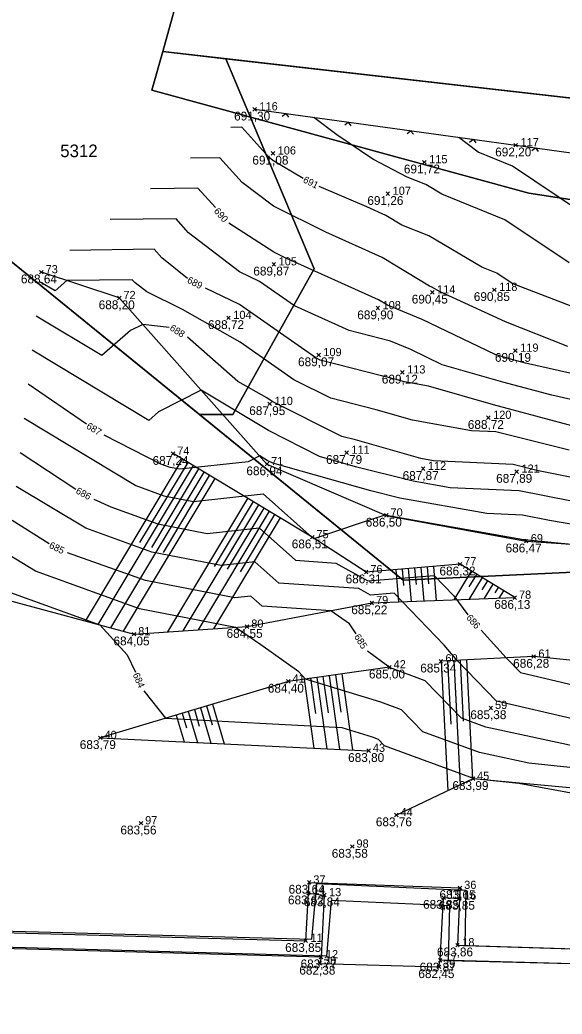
# Model space of a CAD drawing. Extents: x -439750 to -439180, y -1258684 to -1258308.
# Drawn here: x -439519.38 to -439502.17, y -1258511.26 to -1258479.7 of the extents above; entities that cross this region are included whole.
import ezdxf

# ---------------------------------------------------------------- set-up
doc = ezdxf.new("R2010")
doc.units = 0
for name, color, linetype in [('BODY', 7, 'Continuous'), ('CISBOD', 7, 'Continuous'), ('HRANA', 7, 'Continuous'), ('KATASTER', 7, 'Continuous'), ('POLOHOPIS', 7, 'Continuous'), ('SRAFY', 7, 'Continuous'), ('UOV', 7, 'Continuous'), ('VRSTEV', 7, 'Continuous'), ('VYSKY', 7, 'Continuous')]:
    doc.layers.add(name, color=color, linetype=linetype)

# ---------------------------------------------------------------- blocks, each defined once
blk = doc.blocks.new('KRIZEK')
for p, q in [((-2, 0), (2, 0)), ((0, 2), (0, -2))]:
    blk.add_line(p, q)
blk = doc.blocks.new('2123')
blk.add_lwpolyline([(-0.5, -0.5), (0, 0), (0.5, -0.5)])

msp = doc.modelspace()

# ---------------------------------------------------------------- linework, layer by layer
at = {"layer": 'HRANA'}
for points in [[(-439511.54, -1258493.8), (-439516.23, -1258488.53), (-439518.7, -1258487.71)], [(-439519.92, -1258498.08), (-439515.76, -1258499.2), (-439512.17, -1258498.96), (-439508.21, -1258498.21), (-439503.67, -1258498.04), (-439505.41, -1258496.98), (-439508.39, -1258497.23), (-439510.1, -1258496.12), (-439514.52, -1258493.47)], [(-439511.54, -1258493.8), (-439507.75, -1258495.43), (-439503.31, -1258496.25), (-439496.67, -1258496.69), (-439488.09, -1258496.97), (-439481.73, -1258497.12), (-439481.16, -1258497.23), (-439475.66, -1258497.77), (-439471.49, -1258498.09)], [(-439471.88, -1258500.9), (-439476.61, -1258500.46), (-439482.49, -1258500.91), (-439485.2, -1258501.28), (-439488.38, -1258501.74), (-439492.71, -1258501.52), (-439497.17, -1258500.51), (-439503.07, -1258499.91), (-439506.02, -1258500.06)], [(-439507.65, -1258500.25), (-439510.86, -1258500.7), (-439516.83, -1258502.49), (-439508.31, -1258502.9)], [(-439475.58, -1258504.53), (-439478.3, -1258506.13), (-439479.11, -1258504.72), (-439487.55, -1258505.34), (-439492.66, -1258505.61), (-439495.41, -1258504.44), (-439498.85, -1258504.36), (-439505, -1258503.79), (-439507.43, -1258504.94)]]:
    msp.add_lwpolyline(points, dxfattribs=at)
at = {"layer": 'KATASTER'}
for points in [[(-439462.74, -1258442.73), (-439465.13, -1258459.21), (-439469.01, -1258485.93), (-439514.85, -1258480.71), (-439509.68, -1258462.08), (-439512.86, -1258458.3), (-439516.51, -1258455.4), (-439520.66, -1258452.66), (-439525.5, -1258450.78), (-439531.73, -1258450.85), (-439536.69, -1258451.87), (-439541.07, -1258454.21), (-439546.64, -1258459.47)], [(-439546.64, -1258459.47), (-439541.07, -1258454.21), (-439536.69, -1258451.87), (-439531.73, -1258450.85), (-439525.5, -1258450.78), (-439520.66, -1258452.66), (-439516.51, -1258455.4), (-439512.86, -1258458.3), (-439509.68, -1258462.08), (-439514.85, -1258480.71), (-439515.19, -1258481.93), (-439503.22, -1258485.2), (-439495.92, -1258486.32), (-439485.72, -1258487.41), (-439470.33, -1258487.62), (-439429.22, -1258494.1), (-439415.96, -1258495.89), (-439399.97, -1258496.98), (-439400.54, -1258499.28), (-439484.47, -1258496.42), (-439507.21, -1258497.49), (-439520.19, -1258486.95), (-439538.17, -1258484.88), (-439548.5, -1258497.7)], [(-439548.5, -1258497.7), (-439538.17, -1258484.88), (-439520.19, -1258486.95), (-439507.21, -1258497.49), (-439484.47, -1258496.42), (-439400.54, -1258499.28), (-439387.09, -1258499.74), (-439411.19, -1258562.66), (-439413.56, -1258566.65), (-439437.77, -1258626.82), (-439438.12, -1258627.38), (-439482.75, -1258611.76), (-439518.67, -1258591.95), (-439550.54, -1258581.84), (-439567.51, -1258574.36), (-439597.45, -1258561.13)]]:
    msp.add_lwpolyline(points, dxfattribs=at)
for points in [[(-439515.19, -1258481.93), (-439514.85, -1258480.71), (-439469.01, -1258485.93), (-439399.61, -1258493.83), (-439399.2, -1258493.87), (-439399.97, -1258496.98), (-439415.96, -1258495.89), (-439429.22, -1258494.1), (-439470.33, -1258487.62), (-439485.72, -1258487.41), (-439495.92, -1258486.32), (-439503.22, -1258485.2)], [(-439543.31, -1258507.99), (-439510.11, -1258508.88), (-439509.96, -1258507.11), (-439505.22, -1258507.33), (-439505.26, -1258509.08), (-439479.78, -1258509.87), (-439475.62, -1258505.39), (-439475.25, -1258505.73), (-439479.41, -1258510.21), (-439505.77, -1258509.57), (-439505.73, -1258507.82), (-439509.5, -1258507.65), (-439509.65, -1258509.42), (-439543.32, -1258508.49)]]:
    msp.add_lwpolyline(points, close=True, dxfattribs=at)
at = {"layer": 'POLOHOPIS'}
for points in [[(-439511.93, -1258482.54), (-439503.64, -1258483.68), (-439495.23, -1258484.84), (-439489.64, -1258485.55), (-439488, -1258485.65), (-439480.93, -1258486.14), (-439472.63, -1258486.56)], [(-439510.22, -1258507.42), (-439510.2, -1258507.08), (-439505.41, -1258507.25), (-439505.43, -1258507.59)], [(-439491.72, -1258509.46), (-439491.73, -1258509.96), (-439498, -1258509.77), (-439506.04, -1258509.55), (-439505.93, -1258507.56)], [(-439505.93, -1258507.56), (-439505.43, -1258507.59), (-439505.49, -1258509.07), (-439497.99, -1258509.3), (-439491.72, -1258509.46)], [(-439509.82, -1258509.45), (-439509.86, -1258509.65), (-439506.08, -1258509.76), (-439506.04, -1258509.55)]]:
    msp.add_lwpolyline(points, dxfattribs=at)
msp.add_lwpolyline([(-439509.72, -1258507.48), (-439509.82, -1258509.45), (-439529.32, -1258508.92), (-439543.52, -1258508.46), (-439543.4, -1258507.94), (-439529.22, -1258508.41), (-439510.31, -1258508.93), (-439510.22, -1258507.42)], close=True, dxfattribs=at)
at = {"layer": 'SRAFY'}
for p, q in [((-439514.227, -1258493.646), (-439517.307, -1258498.783)), ((-439513.884, -1258493.851), (-439516.906, -1258498.891)), ((-439514.056, -1258493.748), (-439515.581, -1258496.293)), ((-439513.541, -1258494.057), (-439516.504, -1258499)), ((-439513.713, -1258493.954), (-439515.209, -1258496.45)), ((-439513.369, -1258494.16), (-439514.837, -1258496.607)), ((-439513.198, -1258494.263), (-439516.103, -1258499.108)), ((-439512.152, -1258494.89), (-439514.694, -1258499.129)), ((-439511.809, -1258495.095), (-439514.208, -1258499.096)), ((-439511.981, -1258494.992), (-439513.216, -1258497.052)), ((-439511.466, -1258495.301), (-439513.722, -1258499.064)), ((-439511.638, -1258495.198), (-439512.801, -1258497.139)), ((-439511.295, -1258495.404), (-439512.387, -1258497.226)), ((-439511.123, -1258495.507), (-439513.236, -1258499.031)), ((-439507.449, -1258497.151), (-439507.363, -1258498.178)), ((-439507.25, -1258497.134), (-439507.207, -1258497.653)), ((-439507.051, -1258497.118), (-439506.963, -1258498.163)), ((-439506.851, -1258497.101), (-439506.807, -1258497.628)), ((-439506.652, -1258497.084), (-439506.563, -1258498.148)), ((-439506.453, -1258497.067), (-439506.408, -1258497.604)), ((-439506.254, -1258497.051), (-439506.163, -1258498.133)), ((-439505.052, -1258497.198), (-439505.61, -1258498.113)), ((-439504.882, -1258497.302), (-439505.126, -1258497.703)), ((-439504.711, -1258497.406), (-439505.13, -1258498.095)), ((-439504.54, -1258497.51), (-439504.715, -1258497.798)), ((-439504.369, -1258497.614), (-439504.651, -1258498.077)), ((-439504.198, -1258497.718), (-439504.305, -1258497.893)), ((-439504.028, -1258497.822), (-439504.172, -1258498.059)), ((-439506.005, -1258500.059), (-439505.797, -1258504.167)), ((-439505.806, -1258500.049), (-439505.703, -1258502.062)), ((-439505.606, -1258500.039), (-439505.405, -1258503.982)), ((-439505.406, -1258500.029), (-439505.308, -1258501.959)), ((-439505.206, -1258500.019), (-439505.014, -1258503.797)), ((-439509.365, -1258500.49), (-439509.198, -1258501.678)), ((-439509.167, -1258500.463), (-439508.828, -1258502.875)), ((-439510.355, -1258500.629), (-439510.048, -1258502.816)), ((-439510.157, -1258500.601), (-439510.001, -1258501.714)), ((-439509.959, -1258500.574), (-439509.642, -1258502.836)), ((-439509.761, -1258500.546), (-439509.6, -1258501.696)), ((-439509.563, -1258500.518), (-439509.235, -1258502.855)), ((-439513.27, -1258501.423), (-439512.893, -1258502.679)), ((-439514.42, -1258501.767), (-439514.165, -1258502.618)), ((-439514.228, -1258501.71), (-439514.09, -1258502.169)), ((-439514.037, -1258501.652), (-439513.741, -1258502.639)), ((-439513.845, -1258501.595), (-439513.687, -1258502.122)), ((-439513.653, -1258501.538), (-439513.317, -1258502.659)), ((-439513.462, -1258501.48), (-439513.284, -1258502.075))]:
    msp.add_line(p, q, dxfattribs=at)
at = {"layer": 'UOV'}
for points in [[(-439520.19, -1258486.95), (-439538.17, -1258484.88), (-439547.11, -1258495.98), (-439553.31, -1258481.48), (-439550.29, -1258478.38), (-439548.77, -1258475.54), (-439547.7, -1258471.18), (-439548.42, -1258468.53), (-439551.33, -1258468.47), (-439546.64, -1258459.47), (-439541.07, -1258454.21), (-439536.69, -1258451.87), (-439531.73, -1258450.85), (-439525.5, -1258450.78), (-439520.66, -1258452.66), (-439516.51, -1258455.4), (-439512.86, -1258458.3), (-439509.68, -1258462.08), (-439514.85, -1258480.71), (-439512.85, -1258480.94), (-439510.04, -1258487.61), (-439512.62, -1258492.23), (-439513.68, -1258492.23)], [(-439484.47, -1258496.42), (-439507.21, -1258497.49), (-439513.68, -1258492.23), (-439512.62, -1258492.23), (-439510.04, -1258487.61), (-439512.85, -1258480.94), (-439399.2, -1258493.87), (-439444.59, -1258496.79), (-439457.07, -1258497.35)]]:
    msp.add_lwpolyline(points, close=True, dxfattribs=at)
at = {"layer": 'VRSTEV'}
for p, q in [((-439517.264, -1258492.538), (-439519.119, -1258491.268)), ((-439519.373, -1258493.43), (-439517.605, -1258494.6)), ((-439518.453, -1258496.331), (-439519.627, -1258495.593))]:
    msp.add_line(p, q, dxfattribs=at)
for points in [[(-439501.945, -1258487.417), (-439503.99, -1258486.045), (-439505.986, -1258485.231), (-439506.497, -1258484.93), (-439507.087, -1258484.692), (-439508.176, -1258484.125), (-439509.324, -1258483.352), (-439510.051, -1258482.798)], [(-439510.387, -1258484.737), (-439511.348, -1258484.164), (-439511.481, -1258484.063), (-439512.341, -1258483.113), (-439512.686, -1258483.117)], [(-439498.592, -1258486.625), (-439499.716, -1258486.844), (-439499.882, -1258486.862), (-439500.133, -1258486.766), (-439503.739, -1258484.346), (-439504.829, -1258483.901), (-439505.445, -1258483.432)], [(-439501.983, -1258490.065), (-439503.965, -1258489.291), (-439506.041, -1258488.34), (-439506.3, -1258488.187), (-439506.377, -1258488.156), (-439507.879, -1258487.248), (-439509.673, -1258486.441), (-439511.336, -1258485.621), (-439512.329, -1258484.861), (-439513.036, -1258484.081), (-439513.963, -1258484.092)], [(-439496.598, -1258488.747), (-439498.657, -1258489.027), (-439500.691, -1258489.246), (-439503.758, -1258488.068), (-439504.242, -1258487.743), (-439504.714, -1258487.551), (-439506.398, -1258486.559), (-439507.252, -1258486.214), (-439507.761, -1258485.907), (-439508.368, -1258485.633), (-439509.881, -1258484.987)], [(-439513.176, -1258485.661), (-439513.177, -1258485.659), (-439513.731, -1258485.048), (-439515.24, -1258485.067)], [(-439500.78, -1258492.004), (-439502.49, -1258491.617), (-439504.054, -1258491.201), (-439505.975, -1258490.647), (-439506.97, -1258490.168), (-439507.617, -1258489.904), (-439508.925, -1258489.567), (-439510.667, -1258488.783), (-439511.781, -1258488.005), (-439512.406, -1258487.697), (-439514.026, -1258486.457), (-439514.425, -1258486.016), (-439516.517, -1258486.043)], [(-439496.117, -1258491.08), (-439496.994, -1258491.129), (-439497.598, -1258491.21), (-439498.471, -1258491.304), (-439500.847, -1258491.155), (-439503.327, -1258490.595), (-439503.763, -1258490.479), (-439504.298, -1258490.324), (-439506.612, -1258489.211), (-439507.713, -1258488.761), (-439507.997, -1258488.59), (-439510.978, -1258487.248), (-439511.323, -1258487.078), (-439512.748, -1258486.152)], [(-439514.067, -1258487.91), (-439514.874, -1258487.255), (-439515.12, -1258486.984), (-439517.793, -1258487.018)], [(-439501.939, -1258493.364), (-439504.272, -1258492.782), (-439505.04, -1258492.745), (-439506.913, -1258492.407), (-439508.067, -1258492.081), (-439509.506, -1258491.714), (-439510.683, -1258491.123), (-439512.391, -1258489.928), (-439514.219, -1258488.895), (-439515.35, -1258488.338), (-439515.723, -1258488.053), (-439515.815, -1258487.951), (-439517.893, -1258487.978), (-439518.268, -1258488.306), (-439518.737, -1258488.024)], [(-439499.942, -1258492.947), (-439500.712, -1258492.853), (-439501.653, -1258492.64), (-439504.346, -1258491.923), (-439506.411, -1258491.327), (-439507.175, -1258491.189), (-439507.403, -1258491.125), (-439509.854, -1258490.5), (-439509.991, -1258490.431), (-439510.441, -1258490.117), (-439512.406, -1258488.742), (-439513.493, -1258488.215)], [(-439514.646, -1258489.471), (-439515.483, -1258489.369), (-439515.871, -1258489.566), (-439516.777, -1258490.36), (-439518.864, -1258489.105)], [(-439499.624, -1258494.501), (-439499.763, -1258494.503), (-439501.172, -1258494.367), (-439502.967, -1258494.008), (-439503.727, -1258493.818), (-439506.254, -1258493.695), (-439506.65, -1258493.624), (-439508.73, -1258493.037), (-439509.157, -1258492.928), (-439511.375, -1258491.815), (-439511.542, -1258491.699), (-439512.462, -1258491.178), (-439514.064, -1258489.772)], [(-439501.869, -1258494.981), (-439503.527, -1258494.649), (-439505.725, -1258494.551), (-439506.893, -1258494.345), (-439508.728, -1258493.885), (-439509.87, -1258493.562), (-439511.49, -1258492.736), (-439513.625, -1258491.457), (-439514.979, -1258492.145), (-439515.286, -1258492.414), (-439518.991, -1258490.186)], [(-439519.246, -1258492.349), (-439515.702, -1258494.479), (-439514.809, -1258494.805), (-439513.871, -1258494.985), (-439511.656, -1258494.749), (-439510.107, -1258496.13), (-439510.09, -1258496.131), (-439510.039, -1258496.16), (-439508.605, -1258495.681), (-439507.784, -1258495.415), (-439507.754, -1258495.424), (-439507.747, -1258495.426), (-439503.389, -1258496.194), (-439503.317, -1258496.197), (-439503.263, -1258496.208), (-439501.764, -1258496.352)], [(-439499.419, -1258496.131), (-439502.566, -1258495.595), (-439503.422, -1258495.423), (-439504.557, -1258495.373), (-439507.32, -1258494.886), (-439508.241, -1258494.654), (-439511.358, -1258493.774), (-439511.535, -1258493.684), (-439511.767, -1258493.545), (-439512.138, -1258493.734), (-439514.308, -1258493.966), (-439514.614, -1258493.906), (-439514.907, -1258493.8), (-439516.709, -1258492.88)], [(-439501.704, -1258501.92), (-439504.249, -1258501.323), (-439505.505, -1258500.034), (-439505.918, -1258499.545), (-439507.499, -1258497.897), (-439508.256, -1258497.958), (-439508.621, -1258497.755), (-439511.166, -1258497.582), (-439511.92, -1258496.909), (-439512.998, -1258497.025), (-439515.198, -1258496.601), (-439517.294, -1258495.838), (-439519.5, -1258494.512)], [(-439517.032, -1258494.911), (-439516.498, -1258495.159), (-439515.003, -1258495.703), (-439513.435, -1258496.005), (-439511.788, -1258495.829), (-439510.637, -1258496.856), (-439509.355, -1258496.943), (-439508.339, -1258497.509), (-439506.228, -1258497.339), (-439505.609, -1258497.985), (-439505.166, -1258498.588)], [(-439499.015, -1258503.737), (-439503.223, -1258503.297), (-439504.79, -1258502.961), (-439506.592, -1258502.298), (-439507.267, -1258501.606), (-439507.926, -1258501.358), (-439510.318, -1258500.624), (-439510.531, -1258500.391), (-439511.733, -1258499.54), (-439512.538, -1258498.985), (-439515.586, -1258498.397), (-439518.886, -1258497.197), (-439519.755, -1258496.674)], [(-439508.703, -1258499.192), (-439508.919, -1258498.876), (-439509.512, -1258498.457), (-439511.695, -1258498.308), (-439512.052, -1258497.99), (-439512.562, -1258498.044), (-439515.392, -1258497.499), (-439517.87, -1258496.618)], [(-439519.882, -1258497.756), (-439519.681, -1258497.876), (-439516.846, -1258498.908), (-439515.975, -1258499.86), (-439515.717, -1258500.406)], [(-439504.736, -1258499.078), (-439503.946, -1258499.955), (-439503.494, -1258500.418), (-439501.558, -1258500.873), (-439498.408, -1258501.466), (-439497.598, -1258501.499), (-439496.662, -1258501.914), (-439495.288, -1258501.904), (-439493.363, -1258502.099), (-439492.541, -1258502.019), (-439490.79, -1258502.163), (-439488.563, -1258502.359), (-439487.393, -1258502.267), (-439486.431, -1258502.145)], [(-439486.215, -1258503.548), (-439486.548, -1258503.609), (-439488.253, -1258503.838), (-439488.921, -1258503.899), (-439491.202, -1258503.806), (-439492.242, -1258503.849), (-439493.533, -1258503.913), (-439494.708, -1258503.531), (-439495.925, -1258503.518), (-439497.432, -1258503.422), (-439498.301, -1258503.111), (-439499.194, -1258503.057), (-439501.492, -1258502.817), (-439504.585, -1258502.154), (-439505.364, -1258501.867), (-439506.52, -1258500.68), (-439507.651, -1258500.254), (-439507.661, -1258500.251), (-439508.349, -1258499.736)], [(-439515.452, -1258501.003), (-439514.762, -1258501.87), (-439509.16, -1258502.167), (-439508.201, -1258502.461), (-439508.013, -1258502.532), (-439507.821, -1258502.729), (-439504.995, -1258503.769), (-439504.955, -1258503.778), (-439503.546, -1258503.925), (-439499.185, -1258504.733), (-439498.753, -1258504.867), (-439496.279, -1258505.951), (-439495.668, -1258505.858)]]:
    msp.add_lwpolyline(points, dxfattribs=at)

# ---------------------------------------------------------------- block references
at = {"layer": 'BODY', "xscale": 0.04, "yscale": 0.04000000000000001, "rotation": 44.977187}
for p in [(-439511.93, -1258482.54), (-439503.64, -1258483.68), (-439511.35, -1258483.94), (-439506.54, -1258484.22), (-439507.7, -1258485.22), (-439511.32, -1258487.46), (-439518.7, -1258487.71), (-439504.32, -1258488.27), (-439516.23, -1258488.53), (-439506.29, -1258488.35), (-439508.02, -1258488.85), (-439512.76, -1258489.16), (-439503.65, -1258490.2), (-439509.9, -1258490.34), (-439507.24, -1258490.89), (-439511.45, -1258491.89), (-439504.51, -1258492.33), (-439514.52, -1258493.47), (-439509.01, -1258493.44), (-439511.54, -1258493.8), (-439506.58, -1258493.95), (-439503.61, -1258494.04), (-439507.75, -1258495.43), (-439510.1, -1258496.12), (-439503.31, -1258496.25), (-439505.41, -1258496.98), (-439508.39, -1258497.23), (-439503.67, -1258498.04), (-439508.21, -1258498.21), (-439512.17, -1258498.96), (-439515.76, -1258499.2), (-439503.07, -1258499.91), (-439507.65, -1258500.25), (-439506.02, -1258500.06), (-439510.86, -1258500.7), (-439504.43, -1258501.54), (-439516.83, -1258502.49), (-439508.31, -1258502.9), (-439505, -1258503.79), (-439507.43, -1258504.94), (-439515.54, -1258505.2), (-439508.83, -1258505.94), (-439510.2, -1258507.08), (-439510.22, -1258507.42), (-439509.72, -1258507.48), (-439505.93, -1258507.56), (-439505.41, -1258507.25), (-439505.43, -1258507.59), (-439510.31, -1258508.93), (-439505.49, -1258509.07), (-439509.82, -1258509.45), (-439509.86, -1258509.65), (-439506.08, -1258509.76), (-439506.04, -1258509.55)]:
    msp.add_blockref('KRIZEK', p, dxfattribs=at)
at = {"layer": 'POLOHOPIS'}
for p, xscale, yscale, rotation in [((-439510.939, -1258482.676), 0.2, 0.20000000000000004, -7.802843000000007), ((-439508.958, -1258482.949), 0.2, 0.20000000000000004, -7.802843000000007), ((-439506.977, -1258483.221), 0.2, 0.20000000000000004, -7.802843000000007), ((-439504.995, -1258483.494), 0.2, 0.20000000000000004, -7.802843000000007), ((-439503.014, -1258483.766), 0.20000000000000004, 0.2, -7.860138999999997)]:
    msp.add_blockref('2123', p, dxfattribs=dict(at, xscale=xscale, yscale=yscale, rotation=rotation))

# ---------------------------------------------------------------- texts
at = {"layer": 'CISBOD'}
for s, p in [('116', (-439511.778, -1258482.576)), ('117', (-439503.488, -1258483.716)), ('106', (-439511.198, -1258483.976)), ('115', (-439506.388, -1258484.256)), ('107', (-439507.548, -1258485.256)), ('105', (-439511.168, -1258487.496)), ('73', (-439518.567, -1258487.746)), ('114', (-439506.138, -1258488.386)), ('118', (-439504.168, -1258488.306)), ('72', (-439516.097, -1258488.566)), ('108', (-439507.868, -1258488.886)), ('104', (-439512.608, -1258489.196)), ('119', (-439503.498, -1258490.236)), ('109', (-439509.748, -1258490.376)), ('113', (-439507.088, -1258490.926)), ('110', (-439511.298, -1258491.926)), ('120', (-439504.358, -1258492.366)), ('74', (-439514.387, -1258493.506)), ('111', (-439508.858, -1258493.476)), ('71', (-439511.407, -1258493.836)), ('112', (-439506.428, -1258493.986)), ('121', (-439503.458, -1258494.076)), ('70', (-439507.617, -1258495.466)), ('75', (-439509.967, -1258496.156)), ('69', (-439503.162, -1258496.286)), ('76', (-439508.257, -1258497.266)), ('77', (-439505.277, -1258497.016)), ('78', (-439503.537, -1258498.076)), ('79', (-439508.077, -1258498.246)), ('80', (-439512.037, -1258498.996)), ('81', (-439515.627, -1258499.236)), ('60', (-439505.872, -1258500.096)), ('61', (-439502.922, -1258499.946)), ('42', (-439507.517, -1258500.286)), ('41', (-439510.727, -1258500.736)), ('59', (-439504.297, -1258501.576)), ('40', (-439516.697, -1258502.526)), ('43', (-439508.177, -1258502.936)), ('45', (-439504.867, -1258503.826)), ('44', (-439507.297, -1258504.976)), ('97', (-439515.407, -1258505.236)), ('98', (-439508.697, -1258505.976)), ('37', (-439510.067, -1258507.116)), ('36', (-439505.277, -1258507.286)), ('14', (-439510.068, -1258507.456)), ('13', (-439509.568, -1258507.516)), ('15', (-439505.778, -1258507.596)), ('16', (-439505.278, -1258507.626)), ('11', (-439510.158, -1258508.966)), ('18', (-439505.338, -1258509.106)), ('12', (-439509.668, -1258509.486)), ('17', (-439505.888, -1258509.586)), ('38', (-439509.727, -1258509.686)), ('39', (-439505.947, -1258509.796))]:
    msp.add_text(s, height=0.26, dxfattribs=at).set_placement(p)
at = {"layer": 'UOV'}
msp.add_text('5312', height=0.4, dxfattribs=at).set_placement((-439518.104, -1258484.06))
at = {"layer": 'VRSTEV'}
for s, rotation, p in [('691', 333.759, (-439510.414, -1258484.85)), ('690', 311.184, (-439513.239, -1258485.783)), ('689', 332.269, (-439514.094, -1258488.029)), ('688', 326.998, (-439514.648, -1258489.533)), ('687', 328.315, (-439517.295, -1258492.651)), ('686', 331.467, (-439517.631, -1258494.717)), ('685', 333.816, (-439518.477, -1258496.45)), ('686', 311.299, (-439505.23, -1258498.688)), ('685', 302.246, (-439508.782, -1258499.279)), ('684', 293.48, (-439515.806, -1258500.481))]:
    msp.add_text(s, height=0.22, rotation=rotation, dxfattribs=at).set_placement(p)
at = {"layer": 'VYSKY'}
for s, p in [('691,30', (-439512.582, -1258482.896)), ('692,20', (-439504.292, -1258484.036)), ('691,08', (-439512.002, -1258484.296)), ('691,72', (-439507.192, -1258484.576)), ('691,26', (-439508.352, -1258485.576)), ('689,87', (-439511.972, -1258487.816)), ('688,64', (-439519.352, -1258488.066)), ('690,45', (-439506.942, -1258488.706)), ('690,85', (-439504.972, -1258488.626)), ('688,20', (-439516.882, -1258488.886)), ('689,90', (-439508.672, -1258489.206)), ('688,72', (-439513.412, -1258489.516)), ('690,19', (-439504.302, -1258490.556)), ('689,07', (-439510.552, -1258490.696)), ('689,12', (-439507.892, -1258491.246)), ('687,95', (-439512.102, -1258492.246)), ('688,72', (-439505.162, -1258492.686)), ('687,24', (-439515.172, -1258493.826)), ('687,79', (-439509.662, -1258493.796)), ('686,94', (-439512.192, -1258494.156)), ('687,87', (-439507.232, -1258494.306)), ('687,89', (-439504.262, -1258494.396)), ('686,50', (-439508.402, -1258495.786)), ('686,51', (-439510.752, -1258496.476)), ('686,47', (-439503.962, -1258496.606)), ('686,31', (-439509.042, -1258497.586)), ('686,32', (-439506.062, -1258497.336)), ('685,22', (-439508.862, -1258498.566)), ('686,13', (-439504.322, -1258498.396)), ('684,55', (-439512.822, -1258499.316)), ('684,05', (-439516.412, -1258499.556)), ('685,34', (-439506.672, -1258500.416)), ('686,28', (-439503.722, -1258500.266)), ('685,00', (-439508.302, -1258500.606)), ('684,40', (-439511.512, -1258501.056)), ('685,38', (-439505.082, -1258501.896)), ('683,79', (-439517.482, -1258502.846)), ('683,80', (-439508.962, -1258503.256)), ('683,99', (-439505.652, -1258504.146)), ('683,76', (-439508.082, -1258505.296)), ('683,56', (-439516.192, -1258505.556)), ('683,58', (-439509.482, -1258506.296)), ('683,64', (-439510.852, -1258507.436)), ('683,65', (-439506.062, -1258507.606)), ('683,62', (-439510.872, -1258507.776)), ('683,84', (-439510.372, -1258507.836)), ('683,85', (-439506.582, -1258507.916)), ('683,85', (-439506.082, -1258507.946)), ('683,85', (-439510.962, -1258509.286)), ('683,86', (-439506.142, -1258509.426)), ('683,77', (-439510.472, -1258509.806)), ('683,87', (-439506.692, -1258509.906)), ('682,38', (-439510.512, -1258510.006)), ('682,45', (-439506.732, -1258510.116))]:
    msp.add_text(s, height=0.28, dxfattribs=at).set_placement(p)

doc.saveas('drawing.dxf')
